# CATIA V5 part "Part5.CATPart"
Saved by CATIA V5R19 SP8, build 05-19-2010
Part number: Rabatteur_Bas
Bounding box of the stored display mesh (mm): x 6.498 to 6.498, y -400 to 400, z -100 to -65
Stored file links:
  G:\EU_thinkMotion\CFAO_2010\MMS_groupe1\MMS_groupe1\OK\ppiault\piault\piault_cfao\Part5.CATPart
  D:\Catia\Finaltest.CATProduct
  G:\EU_thinkMotion\CFAO_2010\MMS_groupe1\MMS_groupe1\OK\ppiault\piault\piault_cfao\Part2.CATPart
  G:\EU_thinkMotion\CFAO_2010\MMS_groupe1\MMS_groupe1\OK\ppiault\piault\piault_cfao\Part4.CATPart
  G:\Catia Projet\CFAO2\Product2.CATProduct
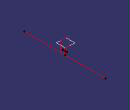
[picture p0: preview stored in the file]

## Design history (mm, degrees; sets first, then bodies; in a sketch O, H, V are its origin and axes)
External parameters (linked from other documents)
  External.DiametreRabatteur = 400 mm
Set1
  Point1: linked copy from another document
  Plane1: linked copy from another document
  Point2: linked copy from another document
Set2
  Line1: type PtDir, RefPoint Point1, Direction Plane1, Start -400 {= -External.DiametreRabatteur}, End 400 {= External.DiametreRabatteur}
  Line2: type PtPt, FirstPoint Point1, SecondPoint Point2
  Line3: type PtDir, RefPoint Point2, Direction Plane1, Start -20, End 20
Body1 (main body)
